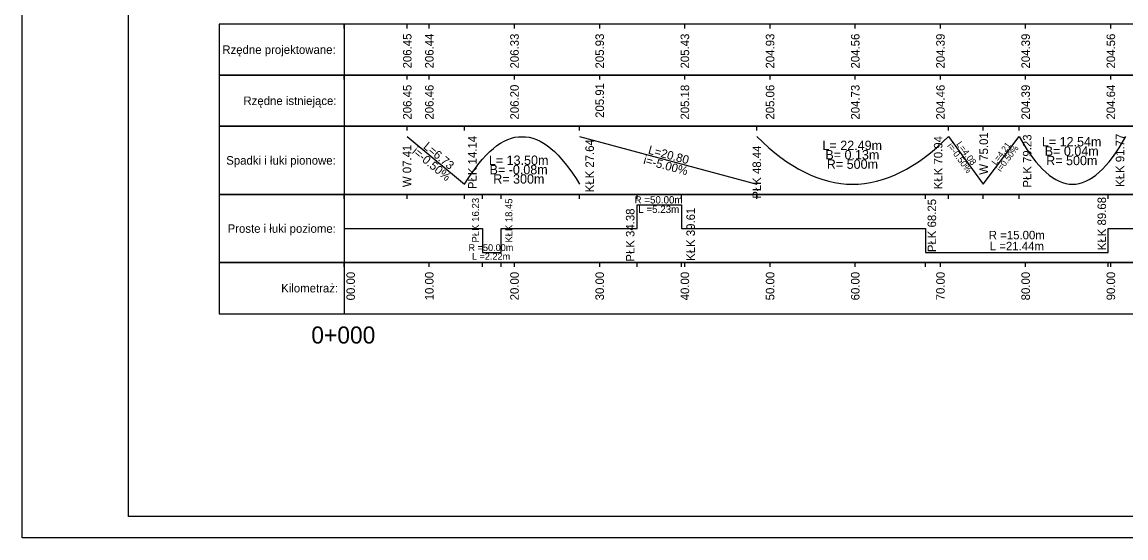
# Model space of a CAD drawing. Extents: x 6513080 to 6513380, y 6022307 to 6022469.
# Drawn here: x 6513079.9 to 6513209.5, y 6022306.7 to 6022367.3 of the extents above; entities that cross this region are included whole.
import ezdxf

# ---------------------------------------------------------------- set-up
doc = ezdxf.new("R2010")
doc.units = 0
for name, color, linetype in [('1', 7, 'Continuous'), ('31', 7, 'Continuous'), ('42', 7, 'Continuous'), ('54', 7, 'Continuous'), ('Level 20', 7, 'Continuous'), ('maxp_ramka_2', 7, 'Continuous')]:
    doc.layers.add(name, color=color, linetype=linetype)

msp = doc.modelspace()

# ---------------------------------------------------------------- linework, layer by layer
for points in [[(6513125.11, 6022353.86), (6513131.84, 6022348.26)], [(6513131.84, 6022348.26), (6513132.26, 6022348.94), (6513132.69, 6022349.57), (6513133.11, 6022350.16), (6513133.53, 6022350.71), (6513133.95, 6022351.21), (6513134.37, 6022351.67), (6513134.8, 6022352.09), (6513135.22, 6022352.46), (6513135.64, 6022352.79), (6513136.06, 6022353.07), (6513136.48, 6022353.31), (6513136.9, 6022353.51), (6513137.33, 6022353.66), (6513137.75, 6022353.77), (6513138.17, 6022353.84), (6513139.01, 6022353.84), (6513139.43, 6022353.77), (6513139.86, 6022353.66), (6513140.28, 6022353.51), (6513140.7, 6022353.31), (6513141.12, 6022353.07), (6513141.54, 6022352.79), (6513141.97, 6022352.46), (6513142.39, 6022352.09), (6513142.81, 6022351.67), (6513143.23, 6022351.21), (6513143.65, 6022350.71), (6513144.07, 6022350.16), (6513144.5, 6022349.57), (6513144.92, 6022348.94), (6513145.34, 6022348.26)], [(6513145.34, 6022353.86), (6513166.14, 6022348.26)], [(6513166.14, 6022353.86), (6513166.85, 6022353.18), (6513167.55, 6022352.55), (6513168.25, 6022351.96), (6513168.96, 6022351.41), (6513169.66, 6022350.91), (6513170.36, 6022350.45), (6513171.06, 6022350.03), (6513171.77, 6022349.66), (6513172.47, 6022349.33), (6513173.17, 6022349.05), (6513173.88, 6022348.81), (6513174.58, 6022348.61), (6513175.28, 6022348.46), (6513175.99, 6022348.35), (6513176.69, 6022348.28), (6513178.09, 6022348.28), (6513178.8, 6022348.35), (6513179.5, 6022348.46), (6513180.2, 6022348.61), (6513180.91, 6022348.81), (6513181.61, 6022349.05), (6513182.31, 6022349.33), (6513183.01, 6022349.66), (6513183.72, 6022350.03), (6513184.42, 6022350.45), (6513185.12, 6022350.91), (6513185.83, 6022351.41), (6513186.53, 6022351.96), (6513187.23, 6022352.55), (6513187.94, 6022353.18), (6513188.64, 6022353.86)], [(6513188.64, 6022353.86), (6513192.72, 6022348.26)], [(6513192.72, 6022348.26), (6513196.93, 6022353.86)], [(6513196.93, 6022353.86), (6513197.32, 6022353.18), (6513197.71, 6022352.55), (6513198.1, 6022351.96), (6513198.5, 6022351.41), (6513198.89, 6022350.91), (6513199.28, 6022350.45), (6513199.67, 6022350.03), (6513200.06, 6022349.66), (6513200.46, 6022349.33), (6513200.85, 6022349.05), (6513201.24, 6022348.81), (6513201.63, 6022348.61), (6513202.02, 6022348.46), (6513202.42, 6022348.35), (6513202.81, 6022348.28), (6513203.59, 6022348.28), (6513203.98, 6022348.35), (6513204.38, 6022348.46), (6513204.77, 6022348.61), (6513205.16, 6022348.81), (6513205.55, 6022349.05), (6513205.94, 6022349.33), (6513206.34, 6022349.66), (6513206.73, 6022350.03), (6513207.12, 6022350.45), (6513207.51, 6022350.91), (6513207.9, 6022351.41), (6513208.29, 6022351.96), (6513208.69, 6022352.55), (6513209.08, 6022353.18), (6513209.47, 6022353.86)], [(6513117.7, 6022343.06), (6513133.93, 6022343.06), (6513133.93, 6022340.26), (6513136.15, 6022340.26), (6513136.15, 6022343.06), (6513152.08, 6022343.06), (6513152.08, 6022345.86), (6513157.31, 6022345.86), (6513157.31, 6022343.06), (6513185.95, 6022343.06), (6513185.95, 6022340.26), (6513207.39, 6022340.26), (6513207.39, 6022343.06), (6513273.67, 6022343.06), (6513273.67, 6022340.26), (6513298.4, 6022340.26), (6513298.4, 6022343.06), (6513316.46, 6022343.06), (6513316.46, 6022343.06), (6513318.13, 6022343.06), (6513318.13, 6022343.06), (6513323.11, 6022343.06)]]:
    msp.add_lwpolyline(points)
at = {"layer": '54'}
for points in [[(6513117.7, 6022367.06), (6513103.03, 6022367.06), (6513103.03, 6022361.06), (6513117.7, 6022361.06)], [(6513117.7, 6022366.56), (6513117.7, 6022367.06)], [(6513125.11, 6022366.56), (6513125.11, 6022367.06)], [(6513127.7, 6022366.56), (6513127.7, 6022367.06)], [(6513137.7, 6022366.56), (6513137.7, 6022367.06)], [(6513147.7, 6022366.56), (6513147.7, 6022367.06)], [(6513157.7, 6022366.56), (6513157.7, 6022367.06)], [(6513167.7, 6022366.56), (6513167.7, 6022367.06)], [(6513177.7, 6022366.56), (6513177.7, 6022367.06)], [(6513187.7, 6022366.56), (6513187.7, 6022367.06)], [(6513197.7, 6022366.56), (6513197.7, 6022367.06)], [(6513207.7, 6022366.56), (6513207.7, 6022367.06)], [(6513117.7, 6022361.06), (6513103.03, 6022361.06), (6513103.03, 6022355.06), (6513117.7, 6022355.06)], [(6513117.7, 6022360.56), (6513117.7, 6022361.06)], [(6513125.11, 6022360.56), (6513125.11, 6022361.06)], [(6513127.7, 6022360.56), (6513127.7, 6022361.06)], [(6513137.7, 6022360.56), (6513137.7, 6022361.06)], [(6513147.7, 6022360.56), (6513147.7, 6022361.06)], [(6513157.7, 6022360.56), (6513157.7, 6022361.06)], [(6513167.7, 6022360.56), (6513167.7, 6022361.06)], [(6513177.7, 6022360.56), (6513177.7, 6022361.06)], [(6513187.7, 6022360.56), (6513187.7, 6022361.06)], [(6513197.7, 6022360.56), (6513197.7, 6022361.06)], [(6513207.7, 6022360.56), (6513207.7, 6022361.06)], [(6513117.7, 6022355.06), (6513103.03, 6022355.06), (6513103.03, 6022347.06), (6513117.7, 6022347.06)], [(6513125.11, 6022354.56), (6513125.11, 6022355.06)], [(6513131.84, 6022354.56), (6513131.84, 6022355.06)], [(6513145.34, 6022354.56), (6513145.34, 6022355.06)], [(6513166.14, 6022354.56), (6513166.14, 6022355.06)], [(6513188.64, 6022354.56), (6513188.64, 6022355.06)], [(6513192.72, 6022354.56), (6513192.72, 6022355.06)], [(6513196.93, 6022354.56), (6513196.93, 6022355.06)], [(6513117.7, 6022347.06), (6513103.03, 6022347.06), (6513103.03, 6022339.06), (6513117.7, 6022339.06)], [(6513117.7, 6022346.56), (6513117.7, 6022347.06)], [(6513125.11, 6022346.56), (6513125.11, 6022347.06)], [(6513131.84, 6022346.56), (6513131.84, 6022347.06)], [(6513133.93, 6022346.56), (6513133.93, 6022347.06)], [(6513136.15, 6022346.56), (6513136.15, 6022347.06)], [(6513145.34, 6022346.56), (6513145.34, 6022347.06)], [(6513152.08, 6022346.56), (6513152.08, 6022347.06)], [(6513157.31, 6022346.56), (6513157.31, 6022347.06)], [(6513166.14, 6022346.56), (6513166.14, 6022347.06)], [(6513185.95, 6022346.56), (6513185.95, 6022347.06)], [(6513188.64, 6022346.56), (6513188.64, 6022347.06)], [(6513192.72, 6022346.56), (6513192.72, 6022347.06)], [(6513196.93, 6022346.56), (6513196.93, 6022347.06)], [(6513207.39, 6022346.56), (6513207.39, 6022347.06)], [(6513117.7, 6022339.06), (6513103.03, 6022339.06), (6513103.03, 6022333.06), (6513117.7, 6022333.06)], [(6513117.7, 6022338.56), (6513117.7, 6022339.06)], [(6513117.7, 6022338.56), (6513117.7, 6022339.06)], [(6513127.7, 6022338.56), (6513127.7, 6022339.06)], [(6513133.93, 6022338.56), (6513133.93, 6022339.06)], [(6513136.15, 6022338.56), (6513136.15, 6022339.06)], [(6513137.7, 6022338.56), (6513137.7, 6022339.06)], [(6513147.7, 6022338.56), (6513147.7, 6022339.06)], [(6513152.08, 6022338.56), (6513152.08, 6022339.06)], [(6513157.31, 6022338.56), (6513157.31, 6022339.06)], [(6513157.7, 6022338.56), (6513157.7, 6022339.06)], [(6513167.7, 6022338.56), (6513167.7, 6022339.06)], [(6513177.7, 6022338.56), (6513177.7, 6022339.06)], [(6513185.95, 6022338.56), (6513185.95, 6022339.06)], [(6513187.7, 6022338.56), (6513187.7, 6022339.06)], [(6513197.7, 6022338.56), (6513197.7, 6022339.06)], [(6513207.39, 6022338.56), (6513207.39, 6022339.06)], [(6513207.7, 6022338.56), (6513207.7, 6022339.06)]]:
    msp.add_lwpolyline(points, dxfattribs=at)
for points in [[(6513117.7, 6022361.06), (6513327.7, 6022361.06), (6513327.7, 6022367.06), (6513117.7, 6022367.06)], [(6513117.7, 6022355.06), (6513327.7, 6022355.06), (6513327.7, 6022361.06), (6513117.7, 6022361.06)], [(6513117.7, 6022347.06), (6513327.7, 6022347.06), (6513327.7, 6022355.06), (6513117.7, 6022355.06)], [(6513117.7, 6022347.06), (6513103.03, 6022347.06), (6513103.03, 6022347.06)], [(6513117.7, 6022339.06), (6513327.7, 6022339.06), (6513327.7, 6022347.06), (6513117.7, 6022347.06)], [(6513117.7, 6022339.06), (6513103.03, 6022339.06), (6513103.03, 6022339.06)], [(6513117.7, 6022333.06), (6513327.7, 6022333.06), (6513327.7, 6022339.06), (6513117.7, 6022339.06)]]:
    msp.add_lwpolyline(points, close=True, dxfattribs=at)
at = {"layer": 'maxp_ramka_2'}
for points in [[(6513079.9, 6022455.24), (6513379.9, 6022455.24), (6513379.9, 6022306.74), (6513079.9, 6022306.74)], [(6513092.4, 6022309.24), (6513092.4, 6022452.74), (6513377.4, 6022452.74), (6513377.4, 6022309.24)]]:
    msp.add_lwpolyline(points, close=True, dxfattribs=at)

# ---------------------------------------------------------------- texts
at = {"layer": '1'}
for s, p in [('206.45', (6513125.61, 6022355.85)), ('206.46', (6513128.2, 6022355.85)), ('206.20', (6513138.2, 6022355.86)), ('205.91', (6513148.2, 6022356.05)), ('205.18', (6513158.2, 6022355.85)), ('205.06', (6513168.2, 6022355.85)), ('204.73', (6513178.2, 6022355.85)), ('204.46', (6513188.2, 6022355.85)), ('204.39', (6513198.2, 6022355.85)), ('204.64', (6513208.2, 6022355.86)), ('W 75.01', (6513193.28, 6022349.38)), ('PŁK 79.23', (6513198.38, 6022347.86)), ('KŁK 91.77', (6513209.28, 6022347.95)), ('W 07.41', (6513125.58, 6022347.92)), ('PŁK 14.14', (6513133.25, 6022347.69)), ('KŁK 27.64', (6513147.02, 6022347.31)), ('PŁK 48.44', (6513166.64, 6022346.56)), ('KŁK 70.94', (6513187.93, 6022347.67))]:
    msp.add_text(s, height=1, rotation=90, dxfattribs=at).set_placement(p)
for s, height, p in [(' Rzędne istniejące: ', 1, (6513105.51, 6022357.56)), ('0+000', 2, (6513113.85, 6022329.56))]:
    msp.add_text(s, height=height, dxfattribs=at).set_placement(p)
at = {"layer": '31'}
for s, p in [('206.45', (6513125.61, 6022361.86)), ('206.44', (6513128.2, 6022361.86)), ('206.33', (6513138.2, 6022361.85)), ('205.93', (6513148.2, 6022361.85)), ('205.43', (6513158.2, 6022361.85)), ('204.93', (6513168.2, 6022361.85)), ('204.56', (6513178.2, 6022361.85)), ('204.39', (6513188.2, 6022361.85)), ('204.39', (6513198.2, 6022361.85)), ('204.56', (6513208.2, 6022361.85))]:
    msp.add_text(s, height=1, rotation=90, dxfattribs=at).set_placement(p)
msp.add_text(' Rzędne projektowane: ', height=1, dxfattribs=at).set_placement((6513103.03, 6022363.56))
at = {"layer": '42'}
for s, p in [('L= 22.49m', (6513173.85, 6022352.27)), ('L= 12.54m', (6513199.6, 6022352.7)), ('B= 0.04m', (6513199.94, 6022351.6)), ('L= 13.50m', (6513134.69, 6022350.53)), ('B= 0.13m', (6513174.19, 6022351.17)), ('R= 500m', (6513200.11, 6022350.5)), ('B= -0.08m', (6513134.77, 6022349.43)), ('R= 500m', (6513174.36, 6022350.07)), ('R= 300m', (6513135.2, 6022348.33))]:
    msp.add_text(s, height=1.1, dxfattribs=at).set_placement(p)
at = {"layer": '54'}
for s, height, p in [('PŁK 16.23', 0.841, (6513133.54, 6022341.41)), ('KŁK 18.45', 0.828, (6513137.45, 6022341.41)), ('PŁK 68.25', 1, (6513187.19, 6022340.29)), ('KŁK 89.68', 1, (6513207.14, 6022340.52)), ('PŁK 34.38', 1, (6513151.78, 6022339.17)), ('KŁK 39.61', 1, (6513158.88, 6022339.26)), ('00.00', 1, (6513118.97, 6022334.63)), ('10.00', 1, (6513128.2, 6022334.63)), ('20.00', 1, (6513138.2, 6022334.63)), ('30.00', 1, (6513148.2, 6022334.63)), ('40.00', 1, (6513158.2, 6022334.63)), ('50.00', 1, (6513168.2, 6022334.63)), ('60.00', 1, (6513178.2, 6022334.63)), ('70.00', 1, (6513188.2, 6022334.63)), ('80.00', 1, (6513198.2, 6022334.63)), ('90.00', 1, (6513208.2, 6022334.63))]:
    msp.add_text(s, height=height, rotation=90, dxfattribs=at).set_placement(p)
for s, height, p in [('R =50.00m', 0.857, (6513151.79, 6022346)), ('L =5.23m', 0.857, (6513152.23, 6022344.89)), (' Proste i łuki poziome: ', 1, (6513103.65, 6022342.56)), ('R =15.00m', 1, (6513193.37, 6022341.79)), ('R =50.00m', 0.801, (6513132.3, 6022340.42)), ('L =21.44m', 1, (6513193.49, 6022340.5)), ('L =2.22m', 0.801, (6513132.7, 6022339.39)), (' Kilometraż: ', 1, (6513109.94, 6022335.56))]:
    msp.add_text(s, height=height, dxfattribs=at).set_placement(p)
at = {"layer": 'Level 20'}
for s, height, rotation, p in [('i=-0.50%', 1, 320.2327, (6513125.61, 6022351.96)), ('L=6.73', 1, 320.2327, (6513126.92, 6022352.55)), ('L=20.80', 1, 344.9343, (6513153.32, 6022351.86)), ('i=-0.50%', 0.762, 306.0559, (6513188.45, 6022352.76)), ('L=4.08', 0.762, 306.0559, (6513189.52, 6022352.96)), ('L=4.21', 0.725, 53.0408, (6513194.21, 6022350.45)), ('i=0.50%', 0.725, 53.0408, (6513194.79, 6022349.66)), ('i=-5.00%', 1, 344.9343, (6513152.76, 6022350.68))]:
    msp.add_text(s, height=height, rotation=rotation, dxfattribs=at).set_placement(p)
msp.add_text(' Spadki i łuki pionowe: ', height=1, dxfattribs=at).set_placement((6513103.49, 6022350.56))

doc.saveas('drawing.dxf')
